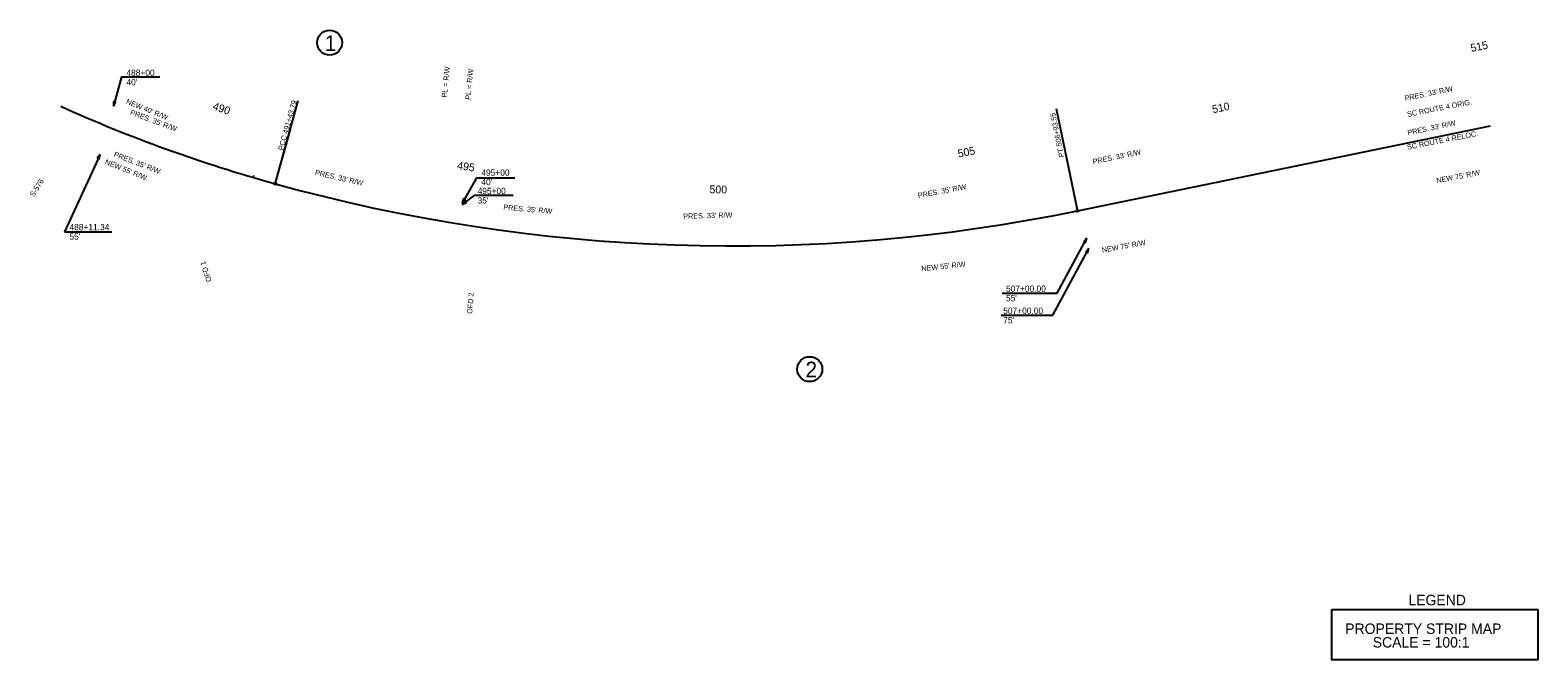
# Model space of a CAD drawing. Extents: x -64038 to -60892, y 1838 to 8465.
# Drawn here: x -63811 to -60927, y 1838 to 3043 of the extents above; entities that cross this region are included whole.
import ezdxf

# ---------------------------------------------------------------- set-up
doc = ezdxf.new("R2010")
doc.units = 0
for name, color, linetype in [('Level 1', 7, 'Continuous'), ('Level 13', 7, 'Continuous'), ('Level 19', 7, 'Continuous'), ('Level 21', 7, 'Continuous'), ('Level 24', 7, 'Continuous'), ('Level 25', 7, 'Continuous'), ('Level 33', 7, 'Continuous')]:
    doc.layers.add(name, color=color, linetype=linetype)

msp = doc.modelspace()

# ---------------------------------------------------------------- linework, layer by layer
at = {"layer": 'Level 1'}
msp.add_lwpolyline([(-61321.2, 1934.3), (-60927.4, 1934.3), (-60927.4, 1838.1), (-61321.2, 1838.1)], close=True, dxfattribs=at)
msp.add_circle((-63342.2, 2748.8), 2, dxfattribs=at)
msp.add_circle((-63342.2, 2748.8), 2, dxfattribs=at)
msp.add_circle((-63342.2, 2748.8), 2, dxfattribs=at)
msp.add_circle((-63342.2, 2748.8), 2, dxfattribs=at)
msp.add_circle((-63342.2, 2748.8), 2, dxfattribs=at)
msp.add_circle((-63342.2, 2748.8), 2, dxfattribs=at)
msp.add_circle((-63342.2, 2748.8), 2, dxfattribs=at)
msp.add_circle((-63342.2, 2748.8), 2, dxfattribs=at)
msp.add_circle((-63342.2, 2748.8), 2, dxfattribs=at)
msp.add_circle((-63342.2, 2748.8), 2, dxfattribs=at)
msp.add_circle((-63342.2, 2748.8), 2, dxfattribs=at)
msp.add_circle((-63342.2, 2748.8), 2, dxfattribs=at)
at = {"layer": 'Level 19'}
for p, q in [((-63341.7, 2750.7), (-63298.3, 2907.4)), ((-61808.2, 2699.1), (-61847.9, 2892.2)), ((-61807.8, 2697.2), (-61017.9, 2859.8)), ((-63341.7, 2750.7), (-63314.1, 2850.5)), ((-63341.7, 2750.7), (-63314.1, 2850.5)), ((-63384.3, 2760.8), (-63383.2, 2764.7)), ((-63342.2, 2748.8), (-63342.2, 2748.8))]:
    msp.add_line(p, q, dxfattribs=at)
for centre in [(-63342.2, 2748.8), (-61807.8, 2697.2)]:
    msp.add_circle(centre, 2, dxfattribs=at)
for centre, radius, start, end in [((-62577.2, 5509.6), 2864.8, 245.7732, 254.5124), ((-62468, 5904), 3274.1, 254.5125, 281.6332)]:
    msp.add_arc(centre, radius, start, end, dxfattribs=at)
at = {"layer": 'Level 24'}
for p, q in [((-63651.8, 2906.5), (-63652, 2897.2)), ((-63652, 2897.2), (-63647.5, 2905.3)), ((-63647.5, 2905.3), (-63651.8, 2906.5)), ((-62979, 2716.5), (-62984.9, 2709.3)), ((-62984.9, 2709.3), (-62976.3, 2712.9)), ((-62982.2, 2720.4), (-62984.6, 2711.5)), ((-62984.6, 2711.5), (-62978.2, 2718.3)), ((-62978.2, 2718.3), (-62982.2, 2720.4)), ((-62976.3, 2712.9), (-62979, 2716.5)), ((-61790.3, 2644.6), (-61796.6, 2637.8)), ((-61796.6, 2637.8), (-61792.6, 2635.6)), ((-61792.6, 2635.6), (-61790.3, 2644.6)), ((-61786.3, 2625), (-61792.6, 2618.2)), ((-61788.6, 2616), (-61786.3, 2625)), ((-61792.6, 2618.2), (-61788.6, 2616))]:
    msp.add_line(p, q, dxfattribs=at)
at = {"layer": 'Level 25'}
for centre in [(-63238.5, 3018.8), (-62320, 2394.2)]:
    msp.add_circle(centre, 23.9, dxfattribs=at)
at = {"layer": 'Level 33'}
for p, q in [((-63636.8, 2953.3), (-63652, 2897.2)), ((-63636.8, 2953.3), (-63563.3, 2953.3)), ((-63677.5, 2805), (-63745.8, 2656.7)), ((-63677.5, 2805), (-63683.3, 2797.8)), ((-63683.3, 2797.8), (-63679.2, 2795.9)), ((-63679.2, 2795.9), (-63677.5, 2805)), ((-62957.8, 2760.1), (-62984.6, 2711.5)), ((-62957.8, 2760.1), (-62884.2, 2760.1)), ((-62961.1, 2727.2), (-62984.9, 2709.3)), ((-62961.1, 2727.2), (-62887.6, 2727.2)), ((-63745.8, 2656.7), (-63654.7, 2656.7)), ((-61855, 2497.2), (-61786.3, 2625)), ((-61846.8, 2539.4), (-61790.3, 2644.6)), ((-61952.2, 2539.4), (-61846.8, 2539.4)), ((-61954, 2497.2), (-61855, 2497.2))]:
    msp.add_line(p, q, dxfattribs=at)

# ---------------------------------------------------------------- texts
at = {"layer": 'Level 1'}
for s, rotation, p in [('OFD 1', 109.0008, (-63463.8, 2563.1)), ('OFD 2', 85.1043, (-62965.8, 2499.7))]:
    msp.add_text(s, height=10, rotation=rotation, dxfattribs=at).set_placement(p)
for s, p in [('LEGEND', (-61175, 1942.6)), ('PROPERTY STRIP MAP', (-61295.8, 1887.7)), ('SCALE = 100:1', (-61243.2, 1861.7))]:
    msp.add_text(s, height=20, dxfattribs=at).set_placement(p)
at = {"layer": 'Level 13'}
for s, rotation, p in [("PRES. 33' R/W", 11.6333, (-61181.1, 2907.4)), ("PRES. 35' R/W", 339.3421, (-63620.8, 2881.6)), ('SC ROUTE 4 ORIG.', 11.0953, (-61176.4, 2876.7)), ("PRES. 33' R/W", 11.6333, (-61175.7, 2841.5)), ('SC ROUTE 4 RELOC.', 11.0953, (-61176.5, 2813.9)), ("PRES. 35' R/W", 338.8367, (-63652.1, 2801.3)), ("PRES. 33' R/W", 11.6333, (-61777.8, 2786.2)), ("PRES. 33' R/W", 347.1087, (-63267.1, 2766)), ('S-576', 58.0243, (-63804.1, 2722.9)), ("PRES. 35' R/W", 10.7462, (-62112.3, 2721.3)), ("PRES. 35' R/W", 355.076, (-62906.5, 2699.3)), ("PRES. 33' R/W", 1.6615, (-62561.9, 2681.7))]:
    msp.add_text(s, height=10, rotation=rotation, dxfattribs=at).set_placement(p)
at = {"layer": 'Level 19'}
for s, rotation, p in [('PCC 491+43.79', 74.5124, (-63327.5, 2811.8)), ('PT 506+93.55', 101.6332, (-61833.1, 2800.4))]:
    msp.add_text(s, height=10, rotation=rotation, dxfattribs=at).set_placement(p)
at = {"layer": 'Level 21'}
for s, rotation, p in [('515', 11.6333, (-61054.5, 3000.8)), ('490', 341.6367, (-63463.3, 2891.1)), ('510', 11.6334, (-61548.7, 2883.7)), ('505', 11.6333, (-62035.3, 2798.9)), ('495', 351.6368, (-62995.1, 2777)), ('500', 359.4962, (-62511.8, 2730.7))]:
    msp.add_text(s, height=15, rotation=rotation, dxfattribs=at).set_placement(p)
at = {"layer": 'Level 25'}
for s, p in [('1', (-63247.9, 3002.8)), ('2', (-62328.3, 2378.5))]:
    msp.add_text(s, height=30, dxfattribs=at).set_placement(p)
for p in [(-63014.3, 2913.3), (-62969.2, 2909.1)]:
    msp.add_text('PL = R/W', height=10, rotation=84.2826, dxfattribs=at).set_placement(p)
at = {"layer": 'Level 33'}
for s, p in [('488+00', (-63627.1, 2955.2)), ("40'", (-63627.1, 2937.2)), ('495+00', (-62948.2, 2764.2)), ('495+00', (-62955.4, 2729.1)), ("40'", (-62948.2, 2746.2)), ("35'", (-62955.4, 2711.1)), ('488+11.34', (-63736, 2660)), ("55'", (-63736, 2642)), ('507+00.00', (-61944.7, 2542.2)), ('507+00.00', (-61950, 2500)), ("55'", (-61944.7, 2524.2)), ("75'", (-61950, 2482))]:
    msp.add_text(s, height=12, dxfattribs=at).set_placement(p)
for s, rotation, p in [("NEW 40' R/W", 337.7515, (-63628.6, 2902.5)), ("NEW 55' R/W", 337.7515, (-63669, 2787.1)), ("NEW 75' R/W", 10.9187, (-61120.4, 2749.9)), ("NEW 75' R/W", 10.3064, (-61760.4, 2616.9)), ("NEW 55' R/W", 6.1735, (-62105.9, 2581.5))]:
    msp.add_text(s, height=10, rotation=rotation, dxfattribs=at).set_placement(p)

doc.saveas('drawing.dxf')
